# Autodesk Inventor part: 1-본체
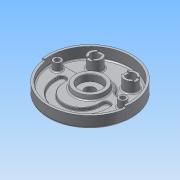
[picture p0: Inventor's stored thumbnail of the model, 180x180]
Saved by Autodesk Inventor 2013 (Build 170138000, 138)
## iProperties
Created: 2015-06
Part Number: 1-본체
Material: 알루미늄 6061
Document SubType Name: Modeling
Designer: Administrator
Density: 2.71 g/cm^3
Mass: 1070.99 g
Surface Area: 1034.49 cm^2
Volume: 395.201 cm^3
Author: Administrator
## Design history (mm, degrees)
sketch "스케치1"
  geometry: C1 r 95 at (0, 0); 1 further point
  constraints: 1 centre point, 1 coincident
  dimensions: "d0" = 190 diameter of C1
extrude "돌출1" new body sketch "스케치1" distance "d2" = 32; taper "d3" = 0 deg
sketch "스케치2"
  geometry: C1 r 95 at (0, 0) reference; C2 r 90 at (0, 0)
  constraints: 1 centre point, 1 coincident
  dimensions: "d4" = 180 diameter of C2
extrude "돌출2" cut sketch "스케치2" distance "d6" = 18; taper "d7" = 0 deg
sketch "스케치3"
  geometry: L1 (-75.657, 16)-(-45.033, 16); L2 (45.033, 16)-(75.657, 16); A1 r 90 centre (0, 0) between (85.114, 29.25) and (-85.114, 29.25); A2 r 42 centre (0, 0) between (36.373, 21) and (-36.373, 21); A3 r 10 centre (-75.657, 26) between (-85.114, 29.25) and (-75.657, 16); A4 r 10 centre (-45.033, 26) between (-45.033, 16) and (-36.373, 21); A5 r 10 centre (45.033, 26) between (36.373, 21) and (45.033, 16); A6 r 10 centre (75.657, 26) between (75.657, 16) and (85.114, 29.25); 5 further points
  constraints: 16 point on circle, 8 tangent, 6 centre point, 4 end point, 4 point on line, 3 equal radius, 2 coincident, 2 horizontal, 1 collinear, 3 other
  dimensions: "d10" = 84 diameter of A2; "d11" = 16 distance from line of L2 point (0, 0); "d12" = 10 radius of A3
extrude "돌출3" cut sketch "스케치3" distance "d13" = 7; taper "d14" = 0 deg
sketch "스케치4"
  geometry: C1 r 15 at (-40, 52); C2 r 15 at (40, 52); A1 r 42 centre (0, 0) between (36.373, 21) and (-36.373, 21) reference
  constraints: 2 centre point, 1 equal radius, 1 horizontal alignment
  dimensions: "d15" = 80 distance of C2.centre C1.centre; "d17" = 40 horizontal distance of A1.centre C2.centre; "d18" = 52 vertical distance of A1.centre C1.centre; "d19" = 30 diameter of C1
extrude "돌출4" join sketch "스케치4" stored distance "d20" = 7; taper "d21" = 0 deg
sketch "스케치5"
  geometry: C1 r 15 at (0, 0) reference; C2 r 15 at (80, 0) reference; 3 further points
  constraints: 2 coincident
hole "구멍1" sketch "스케치5" at (0, 0), (80, 0) diameter "d22" = 20; stored, may be unused: countersink angle "d26" = 90 deg, drill point angle "d28" = 118 deg; dims "d23" = 6, "d24" = 4, "d25" = 2, "d27" = 8
sketch "스케치6"
  geometry: L1 (-6, 13.748)-(-6, -13.748); L2 (6, 13.748)-(6, -13.748); L3 (66.252, 6)-(93.748, 6); L4 (66.252, -6)-(93.748, -6); C1 r 10 at (80, 0) reference; A1 r 15 centre (0, 0) between (-6, 13.748) and (-6, -13.748) reference; A2 r 15 centre (80, 0) between (66.252, 6) and (93.748, 6) reference; 1 further point
  constraints: 8 end point, 8 point on circle, 4 parallel, 1 perpendicular, 1 vertical
  dimensions: "d29" = 12 distance between parallel lines of L2 L1; "d30" = 12 distance between parallel lines of L4 L3
extrude "돌출5" cut sketch "스케치6" distance "d31" = 3; taper "d32" = 0 deg
sketch "스케치7"
  geometry: L1 (0, 0)-(95, 0); L2 (0, 0)-(94.075, -13.221); L3 (0, 0)-(-94.075, -13.221); A1 r 95 centre (0, 0) between (95, 0) and (94.075, -13.221) reference
  constraints: 6 end point, 3 point on circle, 1 horizontal
  dimensions: "d33" = 8 deg angle of L1 L3; "d34" = 8 deg angle of L1 L2
extrude "돌출6" cut sketch "스케치7" distance "d35" = 5; taper "d36" = 0 deg
sketch "스케치10"
  geometry: L1 (-45.033, 16)-(-75.657, 16) reference; L2 (0, -19)-(59, -19); L3 (0, -19)-(-59, -19); L4 (59, -19)-(59, -14); L5 (41, -14)-(41, -19); L6 (-41, -19)-(-41, -14); L7 (-59, -14)-(-59, -19); A1 r 42 centre (0, 0) between (36.373, 21) and (-36.373, 21) reference; A2 r 41 centre (0, -19) between (-41, -19) and (41, -19); A3 r 59 centre (0, -19) between (-59, -19) and (59, -19); A4 r 9 centre (50, -14) between (59, -14) and (41, -14); A5 r 9 centre (-50, -14) between (-41, -14) and (-59, -14)
  constraints: 12 end point, 8 point on circle, 8 tangent, 4 centre point, 4 parallel, 2 point on line, 1 coincident, 1 collinear, 1 horizontal alignment, 1 perpendicular, 1 vertical alignment
  dimensions: "d46" = 41 radius of A2; "d47" = 19 distance of A1.centre A3.centre; "d48" = 59 radius of A3; "d49" = 5 distance of L2.end L4.end
extrude "돌출7" cut sketch "스케치10" distance "d50" = 7; taper "d51" = 0 deg
sketch "스케치11"
  geometry: C1 r 35 at (0, 0); A1 r 90 centre (0, 0) between (-85.114, 29.25) and (85.114, 29.25) reference
  constraints: 1 centre point, 1 coincident
  dimensions: "d52" = 70 diameter of C1
extrude "돌출8" join sketch "스케치11" distance "d54" = 10; taper "d55" = -10 deg
sketch "스케치12"
  geometry: C1 r 35 at (0, 0) reference; C2 r 9 at (-74, 0); C3 r 9 at (74, 0)
  constraints: 2 centre point, 2 horizontal alignment
  dimensions: "d56" = 18 diameter of C2; "d58" = 18 diameter of C3; "d59" = 148 distance of C3.centre C2.centre; "d60" = 74 distance of C2.centre C1.centre
extrude "돌출9" join sketch "스케치12" stored distance "d61" = 10; taper "d62" = 0 deg
sketch "스케치13"
  geometry: C1 r 95 at (0, 0) reference; C2 r 26 at (0, 0)
  constraints: 1 centre point, 1 coincident
  dimensions: "d63" = 52 diameter of C2
extrude "돌출10" join sketch "스케치13" distance "d65" = 12; taper "d66" = -15 deg
sketch "스케치14"
  geometry: C1 r 9 at (-74, 0) reference; C2 r 9 at (74, 0) reference; 2 further points
  constraints: 2 coincident
hole "구멍2" sketch "스케치14" at (-74, 0), (74, 0) diameter "d67" = 11; stored, may be unused: countersink angle "d71" = 90 deg, drill point angle "d73" = 118 deg; dims "d68" = 6, "d69" = 18, "d70" = 11, "d72" = 8
hole "구멍3" diameter "d76" = 23; stored, may be unused: countersink angle "d80" = 90 deg, drill point angle "d82" = 118 deg; dims "d74" = 10, "d75" = 10, "d77" = 6, "d78" = 50, "d79" = 15, "d81" = 8
sketch "스케치15"
  geometry: C1 r 95 at (0, 0) reference; C2 r 68 at (0, 0)
  constraints: 1 centre point, 1 coincident, 1 other
  dimensions: "d83" = 136 diameter of C2
feature "엠보싱1" sketch "스케치15" dims "d10" = 84, "d11" = 16, "d12" = 10, "d85" = 0.5, "d86" = 0
fillet "모깎기1" dims "d87" = 5, "d88" = 0.3, "d89" = 1
chamfer "모따기1" distance "d90" = 1; stored, may be unused: second distance "d91" = 2, angle "d92" = 45 deg
fillet "모깎기2" dims "d93" = 3
node "솔리드1"
other parameters: "d8" = 16, "d39" = 59, "d44" = 59
